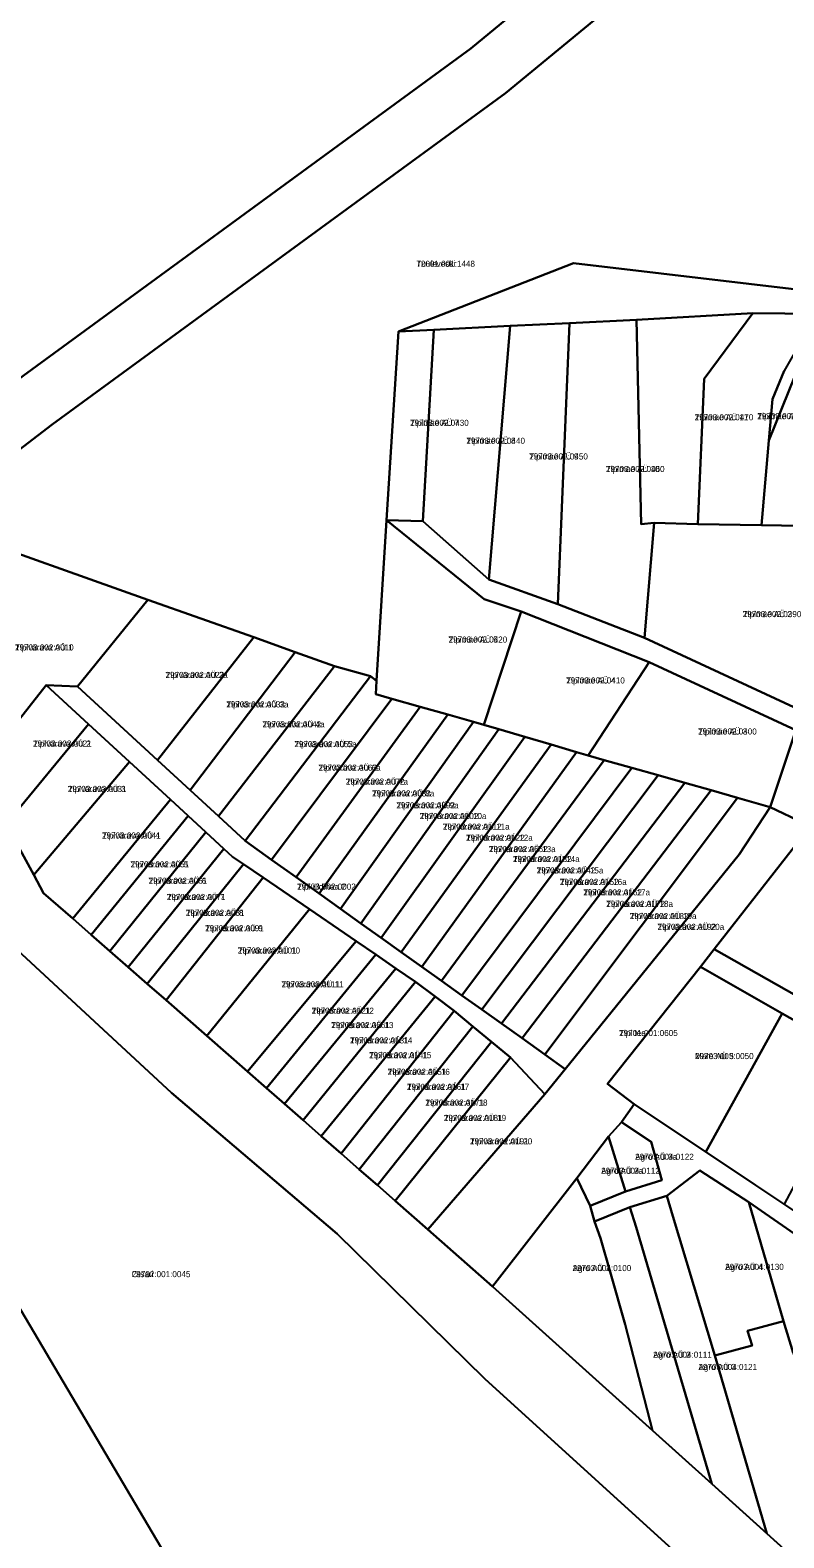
# Model space of a CAD drawing. Extents: x 504287 to 537970, y 6539941 to 6586214.
# Drawn here: x 517831.1 to 518017.5, y 6562193.9 to 6562567.1 of the extents above; entities that cross this region are included whole.
import ezdxf

# ---------------------------------------------------------------- set-up
doc = ezdxf.new("R2010")
doc.units = 0
for name, color, linetype in [('L_AADRESS', 7, 'Continuous'), ('PIIR', 7, 'Continuous'), ('TUNNUS', 7, 'Continuous')]:
    doc.layers.add(name, color=color, linetype=linetype)

msp = doc.modelspace()

# ---------------------------------------------------------------- linework, layer by layer
at = {"layer": 'PIIR'}
for points in [[(517778.2, 6562701.87), (517959.57, 6562883.82), (518080.24, 6562706.33), (518055.42, 6562686.76), (518019.59, 6562636.1), (517989.76, 6562603.54), (517940.1, 6562562.54), (517813.97, 6562470.35), (517799.93, 6562457.34), (517794.03, 6562448.61), (517774.44, 6562458.58), (517669.53, 6562528.36), (517647.31, 6562562.22), (517644.04, 6562559.43), (517629.88, 6562579.78)], [(517811.08, 6562443.57), (517819.81, 6562456.69), (517836.55, 6562469.52), (517907.39, 6562521.29), (517948.7, 6562551.48), (517999.42, 6562593.37), (518015.61, 6562611.04), (518062.26, 6562591.54), (518050.63, 6562558.66), (518032.45, 6562507.14), (518030.55, 6562501.79), (517965.53, 6562509.41), (517922.22, 6562492.52), (517919.25, 6562445.81), (517916.74, 6562406.05), (517915.26, 6562407.19), (517906.42, 6562409.71), (517896.66, 6562413.17), (517886.39, 6562416.83), (517860.21, 6562426.13)], [(517690.73, 6562514.26), (517774.44, 6562458.58), (517794.03, 6562448.61), (517786.38, 6562429.64), (517786.89, 6562414.46), (517791.36, 6562396.31), (517807.8, 6562364.06), (517823.33, 6562343.61), (517866.09, 6562304.05), (517907, 6562269.19), (517943.56, 6562233.31), (517999.07, 6562182.83), (518006.19, 6562174.04), (518011.03, 6562163.1), (518014.41, 6562149.34), (518018.95, 6562101.76), (518022.37, 6562081.47), (518033.82, 6562029.95), (517974.7, 6561990.28), (517892.59, 6562142.19), (517788.03, 6562319.21), (517749.42, 6562395.65), (517678.64, 6562505.89)], [(517964.54, 6562494.62), (517981.1, 6562495.44), (517982.24, 6562444.83), (517985.44, 6562445.14), (517983.09, 6562416.74), (517961.64, 6562425)], [(517981.1, 6562495.44), (518009.88, 6562497.07), (517997.83, 6562480.84), (517996.3, 6562444.82), (517985.44, 6562445.14), (517982.24, 6562444.83)], [(518009.88, 6562497.07), (518025.69, 6562496.93), (518017.61, 6562482.82), (518014.77, 6562475.8), (518013.86, 6562465.56), (518012.03, 6562444.56), (517996.3, 6562444.82), (517997.83, 6562480.84)], [(518028.72, 6562495.86), (518038.34, 6562494.07), (518042.44, 6562485.17), (518036.65, 6562444.14), (518012.03, 6562444.56), (518013.86, 6562465.56), (518020.3, 6562481.49)], [(517922.22, 6562492.52), (517930.94, 6562492.95), (517928.23, 6562445.6), (517919.25, 6562445.81)], [(517930.94, 6562492.95), (517949.8, 6562493.89), (517944.59, 6562431.16), (517928.23, 6562445.6)], [(517949.8, 6562493.89), (517964.54, 6562494.62), (517961.64, 6562425), (517944.59, 6562431.16)], [(517811.08, 6562443.57), (517860.21, 6562426.13), (517842.78, 6562404.66), (517835.02, 6562404.99), (517818.12, 6562383.56), (517803.88, 6562409.79)], [(517919.25, 6562445.81), (517943.38, 6562426.29), (517952.57, 6562423.21), (517943.31, 6562395.2), (517940.81, 6562395.91), (517934.46, 6562397.71), (517927.57, 6562399.66), (517920.55, 6562401.63), (517916.64, 6562402.74), (517916.74, 6562406.05)], [(517985.44, 6562445.14), (517996.3, 6562444.82), (518012.03, 6562444.56), (518036.65, 6562444.14), (518034.82, 6562431.2), (518022.35, 6562398.5), (517983.09, 6562416.74)], [(517860.21, 6562426.13), (517886.39, 6562416.83), (517862.59, 6562386.42), (517842.78, 6562404.66)], [(517952.57, 6562423.21), (517984.2, 6562410.71), (517969.14, 6562387.59), (517966.27, 6562388.43), (517959.97, 6562390.29), (517953.51, 6562392.19), (517947.04, 6562394.1), (517943.31, 6562395.2)], [(517886.39, 6562416.83), (517896.66, 6562413.17), (517870.68, 6562378.97), (517862.59, 6562386.42)], [(517896.66, 6562413.17), (517906.42, 6562409.71), (517877.66, 6562372.53), (517870.68, 6562378.97)], [(517906.42, 6562409.71), (517915.26, 6562407.19), (517884.28, 6562366.43), (517877.66, 6562372.53)], [(517984.2, 6562410.71), (518020.55, 6562393.83), (518014.16, 6562374.82), (518006.09, 6562377.12), (517999.53, 6562378.97), (517993.05, 6562380.81), (517986.42, 6562382.69), (517979.95, 6562384.52), (517973.13, 6562386.45), (517969.14, 6562387.59)], [(517915.26, 6562407.19), (517916.74, 6562406.05), (517916.64, 6562402.74), (517920.55, 6562401.63), (517890.79, 6562361.78), (517884.28, 6562366.43)], [(517835.02, 6562404.99), (517845.51, 6562395.35), (517825.19, 6562370.54), (517818.12, 6562383.56)], [(517835.02, 6562404.99), (517842.78, 6562404.66), (517862.59, 6562386.42), (517870.68, 6562378.97), (517877.66, 6562372.53), (517884.28, 6562366.43), (517890.79, 6562361.78), (517896.9, 6562357.43), (517902.59, 6562353.38), (517907.9, 6562349.59), (517912.89, 6562346.03), (517917.9, 6562342.46), (517922.9, 6562338.9), (517927.95, 6562335.3), (517932.87, 6562331.8), (517937.89, 6562328.21), (517942.83, 6562324.7), (517947.72, 6562321.21), (517952.79, 6562317.59), (517958.43, 6562313.57), (517963.47, 6562309.98), (517958.43, 6562303.77), (517949.91, 6562312.81), (517945.22, 6562316.69), (517940.62, 6562320.49), (517935.96, 6562324.35), (517931.28, 6562327.89), (517926.42, 6562331.57), (517921.59, 6562334.89), (517916.6, 6562338.31), (517911.74, 6562341.65), (517900.23, 6562349.51), (517888.71, 6562357.37), (517883.83, 6562360.69), (517881.16, 6562362.52), (517879.02, 6562364.49), (517874.57, 6562368.59), (517870.21, 6562372.61), (517865.79, 6562376.68), (517855.65, 6562386.01), (517845.51, 6562395.35)], [(517920.55, 6562401.63), (517927.57, 6562399.66), (517896.9, 6562357.43), (517890.79, 6562361.78)], [(517927.57, 6562399.66), (517934.46, 6562397.71), (517902.59, 6562353.38), (517896.9, 6562357.43)], [(517845.51, 6562395.35), (517855.65, 6562386.01), (517831.98, 6562358), (517825.19, 6562370.54)], [(517934.46, 6562397.71), (517940.81, 6562395.91), (517907.9, 6562349.59), (517902.59, 6562353.38)], [(517940.81, 6562395.91), (517943.31, 6562395.2), (517947.04, 6562394.1), (517912.89, 6562346.03), (517907.9, 6562349.59)], [(517947.04, 6562394.1), (517953.51, 6562392.19), (517917.9, 6562342.46), (517912.89, 6562346.03)], [(517953.51, 6562392.19), (517959.97, 6562390.29), (517922.9, 6562338.9), (517917.9, 6562342.46)], [(517959.97, 6562390.29), (517966.27, 6562388.43), (517927.95, 6562335.3), (517922.9, 6562338.9)], [(517966.27, 6562388.43), (517969.14, 6562387.59), (517973.13, 6562386.45), (517932.87, 6562331.8), (517927.95, 6562335.3)], [(517855.65, 6562386.01), (517865.79, 6562376.68), (517841.64, 6562347.21), (517834.4, 6562353.54), (517831.98, 6562358)], [(517973.13, 6562386.45), (517979.95, 6562384.52), (517937.89, 6562328.21), (517932.87, 6562331.8)], [(517979.95, 6562384.52), (517986.42, 6562382.69), (517942.83, 6562324.7), (517937.89, 6562328.21)], [(517986.42, 6562382.69), (517993.05, 6562380.81), (517947.72, 6562321.21), (517942.83, 6562324.7)], [(517993.05, 6562380.81), (517999.53, 6562378.97), (517952.79, 6562317.59), (517947.72, 6562321.21)], [(517865.79, 6562376.68), (517870.21, 6562372.61), (517846.21, 6562343.22), (517841.64, 6562347.21)], [(517999.53, 6562378.97), (518006.09, 6562377.12), (517958.43, 6562313.57), (517952.79, 6562317.59)], [(518006.09, 6562377.12), (518014.16, 6562374.82), (518006.52, 6562363.06), (517963.47, 6562309.98), (517958.43, 6562313.57)], [(517870.21, 6562372.61), (517874.57, 6562368.59), (517850.8, 6562339.18), (517846.21, 6562343.22)], [(517929.51, 6562270.26), (517958.43, 6562303.77), (517963.47, 6562309.98), (518006.52, 6562363.06), (518014.16, 6562374.82), (518022.48, 6562370.82), (518024.09, 6562370.04), (518000.35, 6562339.67), (517996.89, 6562335.29), (517973.96, 6562306.27), (517980.51, 6562301.31), (517977.35, 6562296.81), (517974.16, 6562293.25), (517966.35, 6562282.95), (517945.48, 6562256.14)], [(517874.57, 6562368.59), (517879.02, 6562364.49), (517855.37, 6562335.19), (517850.8, 6562339.18)], [(518024.09, 6562370.04), (518030.03, 6562367.27), (518045.59, 6562360.3), (518026.18, 6562324.94), (518000.35, 6562339.67)], [(517879.02, 6562364.49), (517881.16, 6562362.52), (517883.83, 6562360.69), (517860.06, 6562331.07), (517855.37, 6562335.19)], [(517883.83, 6562360.69), (517888.71, 6562357.37), (517864.72, 6562327), (517860.06, 6562331.07)], [(517888.71, 6562357.37), (517900.23, 6562349.51), (517874.78, 6562318.18), (517864.72, 6562327)], [(517900.23, 6562349.51), (517911.74, 6562341.65), (517884.85, 6562309.38), (517874.78, 6562318.18)], [(517911.74, 6562341.65), (517916.6, 6562338.31), (517889.57, 6562305.23), (517884.85, 6562309.38)], [(518000.35, 6562339.67), (518026.18, 6562324.94), (518046.06, 6562313.61), (518065.5, 6562302.52), (518091.79, 6562287.53), (518082.02, 6562260.36), (518064.67, 6562274.49), (518069.91, 6562285.8), (518052.78, 6562295.33), (518056.17, 6562301.53), (518036.82, 6562312.55), (518017.17, 6562323.75), (517996.89, 6562335.29)], [(517916.6, 6562338.31), (517921.59, 6562334.89), (517894.04, 6562301.32), (517889.57, 6562305.23)], [(517921.59, 6562334.89), (517926.42, 6562331.57), (517898.65, 6562297.28), (517894.04, 6562301.32)], [(517996.89, 6562335.29), (518017.17, 6562323.75), (517998.22, 6562289.48), (517980.51, 6562301.31), (517973.96, 6562306.27)], [(517926.42, 6562331.57), (517931.28, 6562327.89), (517903.1, 6562293.37), (517898.65, 6562297.28)], [(517931.28, 6562327.89), (517935.96, 6562324.35), (517908.03, 6562289.06), (517903.1, 6562293.37)], [(517935.96, 6562324.35), (517940.62, 6562320.49), (517912.51, 6562285.14), (517908.03, 6562289.06)], [(518017.17, 6562323.75), (518036.82, 6562312.55), (518017.63, 6562276.49), (517998.22, 6562289.48)], [(517940.62, 6562320.49), (517945.22, 6562316.69), (517916.99, 6562281.2), (517912.51, 6562285.14)], [(517945.22, 6562316.69), (517949.91, 6562312.81), (517921.38, 6562277.36), (517916.99, 6562281.2)], [(517949.91, 6562312.81), (517958.43, 6562303.77), (517929.51, 6562270.26), (517921.38, 6562277.36)], [(517977.35, 6562296.81), (517984.74, 6562291.98), (517987.37, 6562282.47), (517978.34, 6562279.69), (517974.16, 6562293.25)], [(517966.35, 6562282.95), (517974.16, 6562293.25), (517978.34, 6562279.69), (517969.64, 6562276.11)], [(517966.35, 6562282.95), (517969.64, 6562276.11), (517970.74, 6562272.22), (517972.15, 6562268.1), (517974.71, 6562259.19), (517978.27, 6562246.74), (517985.09, 6562220.54), (517945.48, 6562256.14)], [(517991.68, 6562268.32), (517990.12, 6562273.52), (517988.59, 6562278.6), (517996.8, 6562284.83), (518008.87, 6562277), (518017.47, 6562247.54), (518008.58, 6562245.15), (518009.75, 6562241.57), (518000.47, 6562239.03)], [(517974.71, 6562259.19), (517972.15, 6562268.1), (517970.74, 6562272.22), (517979.48, 6562275.77), (517981.04, 6562270.82), (517999.7, 6562207.32), (517985.09, 6562220.54), (517978.27, 6562246.74)], [(517979.48, 6562275.77), (517988.59, 6562278.6), (517990.12, 6562273.52), (517991.68, 6562268.32), (518000.47, 6562239.03), (518013.37, 6562195.05), (517999.7, 6562207.32), (517981.04, 6562270.82)], [(518008.87, 6562277), (518021.24, 6562268.43), (518028.97, 6562242.21), (518019.83, 6562239.75), (518017.47, 6562247.54)], [(518000.47, 6562239.03), (518009.75, 6562241.57), (518008.58, 6562245.15), (518017.47, 6562247.54), (518019.83, 6562239.75), (518020.71, 6562236.84), (518022.35, 6562231.79), (518026.66, 6562216.7), (518038.41, 6562172.54), (518021.05, 6562188.05), (518013.37, 6562195.05)]]:
    msp.add_lwpolyline(points, close=True, dxfattribs=at)
for points in [[(517813.97, 6562470.35), (517940.1, 6562562.54), (517989.76, 6562603.54)], [(517999.42, 6562593.37), (517948.7, 6562551.48), (517907.39, 6562521.29), (517836.55, 6562469.52), (517819.81, 6562456.69)], [(517629.88, 6562579.78), (517644.04, 6562559.43), (517647.31, 6562562.22), (517669.53, 6562528.36), (517690.73, 6562514.26), (517678.64, 6562505.89), (517749.42, 6562395.65), (517788.03, 6562319.21), (517892.59, 6562142.19), (517974.7, 6561990.28), (517983.26, 6561974.45)], [(518025.69, 6562496.93), (518009.88, 6562497.07), (517981.1, 6562495.44), (517964.54, 6562494.62), (517949.8, 6562493.89), (517930.94, 6562492.95), (517922.22, 6562492.52), (517965.53, 6562509.41), (518030.55, 6562501.79)], [(518020.3, 6562481.49), (518013.86, 6562465.56), (518014.77, 6562475.8), (518017.61, 6562482.82)], [(518022.48, 6562370.82), (518014.16, 6562374.82), (518020.55, 6562393.83), (517984.2, 6562410.71), (517952.57, 6562423.21), (517943.38, 6562426.29), (517919.25, 6562445.81), (517928.23, 6562445.6), (517944.59, 6562431.16), (517961.64, 6562425), (517983.09, 6562416.74), (518022.35, 6562398.5)], [(517825.19, 6562370.54), (517831.98, 6562358), (517834.4, 6562353.54), (517841.64, 6562347.21), (517846.21, 6562343.22), (517850.8, 6562339.18), (517855.37, 6562335.19), (517860.06, 6562331.07), (517864.72, 6562327), (517874.78, 6562318.18), (517884.85, 6562309.38), (517889.57, 6562305.23), (517894.04, 6562301.32), (517898.65, 6562297.28), (517903.1, 6562293.37), (517908.03, 6562289.06), (517912.51, 6562285.14), (517916.99, 6562281.2), (517921.38, 6562277.36), (517929.51, 6562270.26), (517945.48, 6562256.14), (517985.09, 6562220.54), (517999.7, 6562207.32), (518013.37, 6562195.05), (518021.05, 6562188.05)], [(517999.07, 6562182.83), (517943.56, 6562233.31), (517907, 6562269.19), (517866.09, 6562304.05), (517823.33, 6562343.61)], [(518021.24, 6562268.43), (518008.87, 6562277), (517996.8, 6562284.83), (517988.59, 6562278.6), (517979.48, 6562275.77), (517970.74, 6562272.22), (517969.64, 6562276.11), (517978.34, 6562279.69), (517987.37, 6562282.47), (517984.74, 6562291.98), (517977.35, 6562296.81), (517980.51, 6562301.31), (518070.31, 6562241.26)]]:
    msp.add_lwpolyline(points, dxfattribs=at)

# ---------------------------------------------------------------- texts
at = {"layer": 'L_AADRESS'}
for s, p in [('Tuuleveski', (517926.63, 6562508.54)), ('Tipimäe AÜ 7', (517925.09, 6562469.17)), ('Tipimäe AÜ 11', (517995.49, 6562470.55)), ('Tipimäe AÜ 12', (518010.99, 6562470.82)), ('Tipimäe AÜ 8', (517939.01, 6562464.72)), ('Tipimäe AÜ 9', (517954.57, 6562460.84)), ('Tipimäe AÜ 10', (517973.54, 6562457.74)), ('Tipimäe AÜ 2', (518007.38, 6562421.82)), ('Tipimäe AÜ 5', (517934.61, 6562415.53)), ('Tipivärava AÜ 1', (517827.35, 6562413.57)), ('Tipivärava AÜ 2a', (517864.59, 6562406.77)), ('Tipimäe AÜ 4', (517963.71, 6562405.4)), ('Tipivärava AÜ 3a', (517879.62, 6562399.47)), ('Tipivärava AÜ 4a', (517888.55, 6562394.55)), ('Tipimäe AÜ 3', (517996.35, 6562392.77)), ('Tipivärava AÜ 2', (517831.81, 6562389.78)), ('Tipivärava AÜ 5a', (517896.46, 6562389.64)), ('Tipivärava AÜ 6a', (517902.41, 6562383.82)), ('Tipivärava AÜ 3', (517840.42, 6562378.56)), ('Tipivärava AÜ 7a', (517909.18, 6562380.37)), ('Tipivärava AÜ 8a', (517915.68, 6562377.44)), ('Tipivärava AÜ 9a', (517921.7, 6562374.49)), ('Tipivärava AÜ 10a', (517927.47, 6562371.84)), ('Tipivärava AÜ 4', (517848.88, 6562367.03)), ('Tipivärava AÜ 11a', (517933.2, 6562369.22)), ('Tipivärava AÜ 12a', (517938.93, 6562366.48)), ('Tipivärava AÜ 13a', (517944.59, 6562363.66)), ('Tipivärava AÜ 5', (517855.93, 6562359.88)), ('Tipivärava AÜ 14a', (517950.54, 6562361.2)), ('Tipivärava AÜ 6', (517860.39, 6562355.82)), ('Tipivärava AÜ 15a', (517956.41, 6562358.38)), ('Tipivärava AÜ 16a', (517962.16, 6562355.55)), ('Tipivärava AÜ 7', (517864.91, 6562351.82)), ('Tipi üldmaa 2', (517897.14, 6562354.38)), ('Tipivärava AÜ 17a', (517967.94, 6562352.95)), ('Tipivärava AÜ 8', (517869.6, 6562347.89)), ('Tipivärava AÜ 18a', (517973.62, 6562350.11)), ('Tipivärava AÜ 9', (517874.39, 6562344.08)), ('Tipivärava AÜ 19a', (517979.44, 6562347.09)), ('Tipivärava AÜ 20a', (517986.29, 6562344.42)), ('Tipivärava AÜ 10', (517882.47, 6562338.56)), ('Tipivärava AÜ 11', (517893.26, 6562330.2)), ('Tipivärava AÜ 12', (517900.73, 6562323.66)), ('Tipivärava AÜ 13', (517905.58, 6562320.1)), ('Tipi tee', (517976.8, 6562318.14)), ('Tipivärava AÜ 14', (517910.23, 6562316.31)), ('Tipivärava AÜ 15', (517914.96, 6562312.66)), ('Mare AÜ 5', (517995.57, 6562312.43)), ('Tipivärava AÜ 16', (517919.53, 6562308.54)), ('Tipivärava AÜ 17', (517924.32, 6562304.82)), ('Tipivärava AÜ 18', (517928.86, 6562300.92)), ('Tipivärava AÜ 19', (517933.45, 6562297.13)), ('Tipivärava AÜ 20', (517939.91, 6562291.34)), ('Agro AÜ 3a', (517980.76, 6562287.51)), ('Agro AÜ 2a', (517972.35, 6562284.04)), ('Otsari', (517856.23, 6562258.46)), ('Agro AÜ 1', (517965.29, 6562259.96)), ('Agro AÜ 4', (518003.03, 6562260.26)), ('Agro AÜ 2', (517985.22, 6562238.51)), ('Agro AÜ 3', (517996.42, 6562235.49))]:
    msp.add_text(s, height=1.5, dxfattribs=at).set_placement(p)
at = {"layer": 'TUNNUS'}
for s, p in [('72601:001:1448', (517926.63, 6562508.54)), ('29703:002:0430', (517925.09, 6562469.17)), ('29703:002:0470', (517995.49, 6562470.55)), ('29703:002:0480', (518010.99, 6562470.82)), ('29703:002:0440', (517939.01, 6562464.72)), ('29703:002:0450', (517954.57, 6562460.84)), ('29703:002:0460', (517973.54, 6562457.74)), ('29703:002:0390', (518007.38, 6562421.82)), ('29703:002:0420', (517934.61, 6562415.53)), ('29703:002:0010', (517827.35, 6562413.57)), ('29703:002:0022', (517864.59, 6562406.77)), ('29703:002:0410', (517963.71, 6562405.4)), ('29703:002:0032', (517879.62, 6562399.47)), ('29703:002:0042', (517888.55, 6562394.55)), ('29703:002:0021', (517831.81, 6562389.78)), ('29703:002:0052', (517896.46, 6562389.64)), ('29703:002:0400', (517996.35, 6562392.77)), ('29703:002:0062', (517902.41, 6562383.82)), ('29703:002:0031', (517840.42, 6562378.56)), ('29703:002:0072', (517909.18, 6562380.37)), ('29703:002:0082', (517915.68, 6562377.44)), ('29703:002:0092', (517921.7, 6562374.49)), ('29703:002:0102', (517927.47, 6562371.84)), ('29703:002:0041', (517848.88, 6562367.03)), ('29703:002:0112', (517933.2, 6562369.22)), ('29703:002:0122', (517938.93, 6562366.48)), ('29703:002:0662', (517944.59, 6562363.66)), ('29703:002:0051', (517855.93, 6562359.88)), ('29703:002:0132', (517950.54, 6562361.2)), ('29703:002:0061', (517860.39, 6562355.82)), ('29703:002:0142', (517956.41, 6562358.38)), ('29703:002:0152', (517962.16, 6562355.55)), ('29703:002:0071', (517864.91, 6562351.82)), ('29703:002:0002', (517897.14, 6562354.38)), ('29703:002:0162', (517967.94, 6562352.95)), ('29703:002:0172', (517973.62, 6562350.11)), ('29703:002:0081', (517869.6, 6562347.89)), ('29703:002:0182', (517979.44, 6562347.09)), ('29703:002:0192', (517986.29, 6562344.42)), ('29703:002:0091', (517874.39, 6562344.08)), ('29703:002:0101', (517882.47, 6562338.56)), ('29703:002:0111', (517893.26, 6562330.2)), ('29703:002:0121', (517900.73, 6562323.66)), ('29703:002:0661', (517905.58, 6562320.1)), ('29703:002:0131', (517910.23, 6562316.31)), ('29701:001:0605', (517976.8, 6562318.14)), ('29703:002:0141', (517914.96, 6562312.66)), ('29703:003:0050', (517995.57, 6562312.43)), ('29703:002:0151', (517919.53, 6562308.54)), ('29703:002:0161', (517924.32, 6562304.82)), ('29703:002:0171', (517928.86, 6562300.92)), ('29703:002:0181', (517933.45, 6562297.13)), ('29703:002:0191', (517939.91, 6562291.34)), ('29703:004:0122', (517980.76, 6562287.51)), ('29703:004:0112', (517972.35, 6562284.04)), ('29703:004:0100', (517965.29, 6562259.96)), ('29703:004:0130', (518003.03, 6562260.26)), ('29702:001:0045', (517856.23, 6562258.46)), ('29703:004:0111', (517985.22, 6562238.51)), ('29703:004:0121', (517996.42, 6562235.49))]:
    msp.add_text(s, height=1.5, dxfattribs=at).set_placement(p)

doc.saveas('drawing.dxf')
